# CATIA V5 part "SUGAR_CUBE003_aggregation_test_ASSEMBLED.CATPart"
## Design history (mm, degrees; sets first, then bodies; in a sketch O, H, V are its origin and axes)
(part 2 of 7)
Body8 "sugar_cube003_Ab002"
  Line62: type PtDir, RefPoint Point10, Direction edge [XY plane of AxisSystem1 | ZX plane of AxisSystem1], Start 0, End 3048 {= Body8.X1}
  Line63: type PtDir, RefPoint Point10, Direction edge [XY plane of AxisSystem1 | ZX plane of AxisSystem1], Start 0, End 3657.6 {= Body8.X2}
  Line64: type PtDir, RefPoint Point10, Direction edge [YZ plane of AxisSystem1 | XY plane of AxisSystem1], Start 0, End 3962.4 {= Body8.Y1}
  Line65: type PtDir, RefPoint Point10, Direction edge [YZ plane of AxisSystem1 | XY plane of AxisSystem1], Start 0, End 4876.8 {= Body8.Y2}
  Line66: type PtDir, RefPoint Point10, Direction edge [ZX plane of AxisSystem1 | YZ plane of AxisSystem1], Start 0, End 3962.4 {= Body8.Z1}
  Line67: type PtDir, RefPoint Point10, Direction edge [ZX plane of AxisSystem1 | YZ plane of AxisSystem1], Start 0, End 4876.8 {= Body8.Z2}
  Plane89: type Normal, Curve Line62, RefPoint vertex of Line62
  Plane90: type Normal, Curve Line63, RefPoint vertex of Line63
  Plane91: type Normal, Curve Line64, RefPoint vertex of Line64
  Plane92: type Normal, Curve Line65, RefPoint vertex of Line65
  Plane93: type Normal, Curve Line66, RefPoint vertex of Line66
  Plane94: type Normal, Curve Line67, RefPoint vertex of Line67
  Plane95: type 3Points, Element1 Point10, Element2 vertex of Line64, Element3 vertex of Line62
  Intersect121: ToIntersect1 Plane91, ToIntersect2 Plane90
  Intersect122: ToIntersect1 Plane89, ToIntersect2 Plane91
  Intersect123: ToIntersect1 Plane89, ToIntersect2 Plane92
  Intersect124: ToIntersect1 Plane92, ToIntersect2 Plane90
  MultiSel7
  LineCorner7: Elements ({intersect ToIntersect1 Plane95, ToIntersect2 Intersect123}; {intersect ToIntersect1 Plane95, ToIntersect2 Intersect124}; {intersect ToIntersect1 Plane95, ToIntersect2 Intersect121}; {intersect ToIntersect1 Plane95, ToIntersect2 Intersect122})
  Pad26: profile LineCorner7, up to Plane93, opposite side up to Plane94, deactivated
  Plane96: type Offset, RefPlane Plane92, Offset 609.6 {= thickness}
  Plane97: type Offset, RefPlane Plane91, Offset 609.6 {= thickness}, reversed
  Plane98: type Offset, RefPlane Plane89, Offset 609.6 {= thickness}, reversed
  Plane99: type Offset, RefPlane Plane90, Offset 609.6 {= thickness}
  Plane100: type Offset, RefPlane Plane94, Offset 609.6 {= thickness}
  Plane101: type Offset, RefPlane Plane93, Offset 609.6 {= thickness}, reversed
  Intersect125: ToIntersect1 Plane96, ToIntersect2 Plane89
  Intersect126: ToIntersect1 Plane97, ToIntersect2 Plane89
  Intersect127: ToIntersect1 Plane100, ToIntersect2 Plane89
  Intersect128: ToIntersect1 Plane101, ToIntersect2 Plane89
  Trim73: Trimmed (Intersect125; Intersect128)
  Trim74: Trimmed (Trim73; Intersect126)
  Trim75: Trimmed (Trim74; Intersect127)
  Pocket30: profile Trim75, up to Plane99, deactivated
  Pad27: profile LineCorner7, up to Plane93, opposite side up to Plane94, deactivated
  Intersect129: ToIntersect1 Plane97, ToIntersect2 Plane90
  Intersect130: ToIntersect1 Plane90, ToIntersect2 Plane96
  Intersect131: ToIntersect1 Plane100, ToIntersect2 Plane90
  Intersect132: ToIntersect1 Plane101, ToIntersect2 Plane90
  Trim76: Trimmed (Intersect132; Intersect129)
  Trim77: Trimmed (Trim76; Intersect131)
  Trim78: Trimmed (Trim77; Intersect130)
  Pocket31: profile Trim78, up to Plane98, deactivated
  Intersect133: ToIntersect1 Plane99, ToIntersect2 Plane92
  Intersect134: ToIntersect1 Plane100, ToIntersect2 Plane92
  Intersect135: ToIntersect1 Plane92, ToIntersect2 Plane98
  Intersect136: ToIntersect1 Plane101, ToIntersect2 Plane92
  Trim79: Trimmed (Intersect133; Intersect136)
  Trim80: Trimmed (Trim79; Intersect135)
  Trim81: Trimmed (Trim80; Intersect134)
  Pad28: profile LineCorner7, up to Plane93, opposite side up to Plane94, deactivated
  Pocket32: profile Trim81, up to Plane97, deactivated
  Intersect137: ToIntersect1 Plane98, ToIntersect2 Plane91
  Intersect138: ToIntersect1 Plane100, ToIntersect2 Plane91
  Intersect139: ToIntersect1 Plane99, ToIntersect2 Plane91
  Intersect140: ToIntersect1 Plane101, ToIntersect2 Plane91
  Trim82: Trimmed (Intersect137; Intersect140)
  Trim83: Trimmed (Trim82; Intersect139)
  Trim84: Trimmed (Trim83; Intersect138)
  Pad29: profile LineCorner7, up to Plane93, opposite side up to Plane94, deactivated
  Pocket33: profile Trim84, up to Plane96, deactivated
Body9 "sugar_cube003_Ac002"
  Line68: type PtDir, RefPoint Point6, Direction edge [XY plane of AxisSystem1 | ZX plane of AxisSystem1], Start 0, End 5181.6 {= Body9.X1}
  Line69: type PtDir, RefPoint Point6, Direction edge [XY plane of AxisSystem1 | ZX plane of AxisSystem1], Start 0, End 3962.4 {= Body9.X2}
  Line70: type PtDir, RefPoint Point6, Direction edge [YZ plane of AxisSystem1 | XY plane of AxisSystem1], Start 0, End 5791.2 {= Body9.Y1}
  Line71: type PtDir, RefPoint Point6, Direction edge [YZ plane of AxisSystem1 | XY plane of AxisSystem1], Start 0, End 5181.6 {= Body9.Y2}
  Line72: type PtDir, RefPoint Point6, Direction edge [ZX plane of AxisSystem1 | YZ plane of AxisSystem1], Start 0, End 6096 {= Body9.Z1}
  Line73: type PtDir, RefPoint Point6, Direction edge [ZX plane of AxisSystem1 | YZ plane of AxisSystem1], Start 0, End 5791.2 {= Body9.Z2}
  Plane102: type Normal, Curve Line68, RefPoint vertex of Line68
  Plane103: type Normal, Curve Line69, RefPoint vertex of Line69
  Plane104: type Normal, Curve Line70, RefPoint vertex of Line70
  Plane105: type Normal, Curve Line71, RefPoint vertex of Line71
  Plane106: type Normal, Curve Line72, RefPoint vertex of Line72
  Plane107: type Normal, Curve Line73, RefPoint vertex of Line73
  Plane108: type 3Points, Element1 Point6, Element2 vertex of Line70, Element3 vertex of Line68
  Intersect141: ToIntersect1 Plane104, ToIntersect2 Plane103
  Intersect142: ToIntersect1 Plane102, ToIntersect2 Plane104
  Intersect143: ToIntersect1 Plane102, ToIntersect2 Plane105
  Intersect144: ToIntersect1 Plane105, ToIntersect2 Plane103
  MultiSel8
  LineCorner8: Elements ({intersect ToIntersect1 Plane108, ToIntersect2 Intersect143}; {intersect ToIntersect1 Plane108, ToIntersect2 Intersect144}; {intersect ToIntersect1 Plane108, ToIntersect2 Intersect141}; {intersect ToIntersect1 Plane108, ToIntersect2 Intersect142})
  Pad30: profile LineCorner8, up to Plane106, opposite side up to Plane107
  Plane109: type Offset, RefPlane Plane105, Offset 609.6 {= thickness}
  Plane110: type Offset, RefPlane Plane104, Offset 609.6 {= thickness}, reversed
  Plane111: type Offset, RefPlane Plane102, Offset 609.6 {= thickness}, reversed
  Plane112: type Offset, RefPlane Plane103, Offset 609.6 {= thickness}
  Plane113: type Offset, RefPlane Plane107, Offset 609.6 {= thickness}
  Plane114: type Offset, RefPlane Plane106, Offset 609.6 {= thickness}, reversed
  Intersect145: ToIntersect1 Plane109, ToIntersect2 Plane102
  Intersect146: ToIntersect1 Plane110, ToIntersect2 Plane102
  Intersect147: ToIntersect1 Plane113, ToIntersect2 Plane102
  Intersect148: ToIntersect1 Plane114, ToIntersect2 Plane102
  Trim85: Trimmed (Intersect145; Intersect148)
  Trim86: Trimmed (Trim85; Intersect146)
  Trim87: Trimmed (Trim86; Intersect147)
  Pocket34: profile Trim87, up to Plane112, deactivated
  Pad31: profile LineCorner8, up to Plane106, opposite side up to Plane107
  Intersect149: ToIntersect1 Plane110, ToIntersect2 Plane103
  Intersect150: ToIntersect1 Plane103, ToIntersect2 Plane109
  Intersect151: ToIntersect1 Plane113, ToIntersect2 Plane103
  Intersect152: ToIntersect1 Plane114, ToIntersect2 Plane103
  Trim88: Trimmed (Intersect152; Intersect149)
  Trim89: Trimmed (Trim88; Intersect151)
  Trim90: Trimmed (Trim89; Intersect150)
  Pocket35: profile Trim90, up to Plane111
  Intersect153: ToIntersect1 Plane112, ToIntersect2 Plane105
  Intersect154: ToIntersect1 Plane113, ToIntersect2 Plane105
  Intersect155: ToIntersect1 Plane105, ToIntersect2 Plane111
  Intersect156: ToIntersect1 Plane114, ToIntersect2 Plane105
  Trim91: Trimmed (Intersect153; Intersect156)
  Trim92: Trimmed (Trim91; Intersect155)
  Trim93: Trimmed (Trim92; Intersect154)
  Pad32: profile LineCorner8, up to Plane106, opposite side up to Plane107, deactivated
  Pocket36: profile Trim93, up to Plane110, deactivated
  Intersect157: ToIntersect1 Plane111, ToIntersect2 Plane104
  Intersect158: ToIntersect1 Plane113, ToIntersect2 Plane104
  Intersect159: ToIntersect1 Plane112, ToIntersect2 Plane104
  Intersect160: ToIntersect1 Plane114, ToIntersect2 Plane104
  Trim94: Trimmed (Intersect157; Intersect160)
  Trim95: Trimmed (Trim94; Intersect159)
  Trim96: Trimmed (Trim95; Intersect158)
  Pad33: profile LineCorner8, up to Plane106, opposite side up to Plane107, deactivated
  Pocket37: profile Trim96, up to Plane109, deactivated
Body10 "sugar_cube003_Ad002"
  Line74: type PtDir, RefPoint Point2, Direction edge [XY plane of AxisSystem1 | ZX plane of AxisSystem1], Start 0, End 5486.4 {= Body10.X1}
  Line75: type PtDir, RefPoint Point2, Direction edge [XY plane of AxisSystem1 | ZX plane of AxisSystem1], Start 0, End 4876.8 {= Body10.X2}
  Line76: type PtDir, RefPoint Point2, Direction edge [YZ plane of AxisSystem1 | XY plane of AxisSystem1], Start 0, End 3962.4 {= Body10.Y1}
  Line77: type PtDir, RefPoint Point2, Direction edge [YZ plane of AxisSystem1 | XY plane of AxisSystem1], Start 0, End 3962.4 {= Body10.Y2}
  Line78: type PtDir, RefPoint Point2, Direction edge [ZX plane of AxisSystem1 | YZ plane of AxisSystem1], Start 0, End 6096 {= Body10.Z1}
  Line79: type PtDir, RefPoint Point2, Direction edge [ZX plane of AxisSystem1 | YZ plane of AxisSystem1], Start 0, End 3657.6 {= Body10.Z2}
  Plane115: type Normal, Curve Line74, RefPoint vertex of Line74
  Plane116: type Normal, Curve Line75, RefPoint vertex of Line75
  Plane117: type Normal, Curve Line76, RefPoint vertex of Line76
  Plane118: type Normal, Curve Line77, RefPoint vertex of Line77
  Plane119: type Normal, Curve Line78, RefPoint vertex of Line78
  Plane120: type Normal, Curve Line79, RefPoint vertex of Line79
  Plane121: type 3Points, Element1 Point2, Element2 vertex of Line76, Element3 vertex of Line74
  Intersect161: ToIntersect1 Plane117, ToIntersect2 Plane116
  Intersect162: ToIntersect1 Plane115, ToIntersect2 Plane117
  Intersect163: ToIntersect1 Plane115, ToIntersect2 Plane118
  Intersect164: ToIntersect1 Plane118, ToIntersect2 Plane116
  MultiSel9
  LineCorner9: Elements ({intersect ToIntersect1 Plane121, ToIntersect2 Intersect163}; {intersect ToIntersect1 Plane121, ToIntersect2 Intersect164}; {intersect ToIntersect1 Plane121, ToIntersect2 Intersect161}; {intersect ToIntersect1 Plane121, ToIntersect2 Intersect162})
  Pad34: profile LineCorner9, up to Plane119, opposite side up to Plane120, deactivated
  Plane122: type Offset, RefPlane Plane118, Offset 609.6 {= thickness}
  Plane123: type Offset, RefPlane Plane117, Offset 609.6 {= thickness}, reversed
  Plane124: type Offset, RefPlane Plane115, Offset 609.6 {= thickness}, reversed
  Plane125: type Offset, RefPlane Plane116, Offset 609.6 {= thickness}
  Plane126: type Offset, RefPlane Plane120, Offset 609.6 {= thickness}
  Plane127: type Offset, RefPlane Plane119, Offset 609.6 {= thickness}, reversed
  Intersect165: ToIntersect1 Plane122, ToIntersect2 Plane115
  Intersect166: ToIntersect1 Plane123, ToIntersect2 Plane115
  Intersect167: ToIntersect1 Plane126, ToIntersect2 Plane115
  Intersect168: ToIntersect1 Plane127, ToIntersect2 Plane115
  Trim97: Trimmed (Intersect165; Intersect168)
  Trim98: Trimmed (Trim97; Intersect166)
  Trim99: Trimmed (Trim98; Intersect167)
  Pocket38: profile Trim99, up to Plane125, deactivated
  Pad35: profile LineCorner9, up to Plane119, opposite side up to Plane120, deactivated
  Intersect169: ToIntersect1 Plane123, ToIntersect2 Plane116
  Intersect170: ToIntersect1 Plane116, ToIntersect2 Plane122
  Intersect171: ToIntersect1 Plane126, ToIntersect2 Plane116
  Intersect172: ToIntersect1 Plane127, ToIntersect2 Plane116
  Trim100: Trimmed (Intersect172; Intersect169)
  Trim101: Trimmed (Trim100; Intersect171)
  Trim102: Trimmed (Trim101; Intersect170)
  Pocket39: profile Trim102, up to Plane124, deactivated
  Intersect173: ToIntersect1 Plane125, ToIntersect2 Plane118
  Intersect174: ToIntersect1 Plane126, ToIntersect2 Plane118
  Intersect175: ToIntersect1 Plane118, ToIntersect2 Plane124
  Intersect176: ToIntersect1 Plane127, ToIntersect2 Plane118
  Trim103: Trimmed (Intersect173; Intersect176)
  Trim104: Trimmed (Trim103; Intersect175)
  Trim105: Trimmed (Trim104; Intersect174)
  Pad36: profile LineCorner9, up to Plane119, opposite side up to Plane120, deactivated
  Pocket40: profile Trim105, up to Plane123, deactivated
  Intersect177: ToIntersect1 Plane124, ToIntersect2 Plane117
  Intersect178: ToIntersect1 Plane126, ToIntersect2 Plane117
  Intersect179: ToIntersect1 Plane125, ToIntersect2 Plane117
  Intersect180: ToIntersect1 Plane127, ToIntersect2 Plane117
  Trim106: Trimmed (Intersect177; Intersect180)
  Trim107: Trimmed (Trim106; Intersect179)
  Trim108: Trimmed (Trim107; Intersect178)
  Pad37: profile LineCorner9, up to Plane119, opposite side up to Plane120, deactivated
  Pocket41: profile Trim108, up to Plane122, deactivated
Body11 "sugar_cube003_Ae002"
  Line80: type PtDir, RefPoint Point98, Direction edge [XY plane of AxisSystem1 | ZX plane of AxisSystem1], Start 0, End 4267.2 {= Body11.X1}
  Line81: type PtDir, RefPoint Point98, Direction edge [XY plane of AxisSystem1 | ZX plane of AxisSystem1], Start 0, End 3657.6 {= Body11.X2}
  Line82: type PtDir, RefPoint Point98, Direction edge [YZ plane of AxisSystem1 | XY plane of AxisSystem1], Start 0, End 5486.4 {= Body11.Y1}
  Line83: type PtDir, RefPoint Point98, Direction edge [YZ plane of AxisSystem1 | XY plane of AxisSystem1], Start 0, End 3048 {= Body11.Y2}
  Line84: type PtDir, RefPoint Point98, Direction edge [ZX plane of AxisSystem1 | YZ plane of AxisSystem1], Start 0, End 5181.6 {= Body11.Z1}
  Line85: type PtDir, RefPoint Point98, Direction edge [ZX plane of AxisSystem1 | YZ plane of AxisSystem1], Start 0, End 3048 {= Body11.Z2}
  Plane128: type Normal, Curve Line80, RefPoint vertex of Line80
  Plane129: type Normal, Curve Line81, RefPoint vertex of Line81
  Plane130: type Normal, Curve Line82, RefPoint vertex of Line82
  Plane131: type Normal, Curve Line83, RefPoint vertex of Line83
  Plane132: type Normal, Curve Line84, RefPoint vertex of Line84
  Plane133: type Normal, Curve Line85, RefPoint vertex of Line85
  Plane134: type 3Points, Element1 Point98, Element2 vertex of Line82, Element3 vertex of Line80
  Intersect181: ToIntersect1 Plane130, ToIntersect2 Plane129
  Intersect182: ToIntersect1 Plane128, ToIntersect2 Plane130
  Intersect183: ToIntersect1 Plane128, ToIntersect2 Plane131
  Intersect184: ToIntersect1 Plane131, ToIntersect2 Plane129
  MultiSel10
  LineCorner10: Elements ({intersect ToIntersect1 Plane134, ToIntersect2 Intersect183}; {intersect ToIntersect1 Plane134, ToIntersect2 Intersect184}; {intersect ToIntersect1 Plane134, ToIntersect2 Intersect181}; {intersect ToIntersect1 Plane134, ToIntersect2 Intersect182})
  Pad38: profile LineCorner10, up to Plane132, opposite side up to Plane133, deactivated
  Plane135: type Offset, RefPlane Plane131, Offset 609.6 {= thickness}
  Plane136: type Offset, RefPlane Plane130, Offset 609.6 {= thickness}, reversed
  Plane137: type Offset, RefPlane Plane128, Offset 609.6 {= thickness}, reversed
  Plane138: type Offset, RefPlane Plane129, Offset 609.6 {= thickness}
  Plane139: type Offset, RefPlane Plane133, Offset 609.6 {= thickness}
  Plane140: type Offset, RefPlane Plane132, Offset 609.6 {= thickness}, reversed
  Intersect185: ToIntersect1 Plane135, ToIntersect2 Plane128
  Intersect186: ToIntersect1 Plane136, ToIntersect2 Plane128
  Intersect187: ToIntersect1 Plane139, ToIntersect2 Plane128
  Intersect188: ToIntersect1 Plane140, ToIntersect2 Plane128
  Trim109: Trimmed (Intersect185; Intersect188)
  Trim110: Trimmed (Trim109; Intersect186)
  Trim111: Trimmed (Trim110; Intersect187)
  Pocket42: profile Trim111, up to Plane138, deactivated
  Pad39: profile LineCorner10, up to Plane132, opposite side up to Plane133, deactivated
  Intersect189: ToIntersect1 Plane136, ToIntersect2 Plane129
  Intersect190: ToIntersect1 Plane129, ToIntersect2 Plane135
  Intersect191: ToIntersect1 Plane139, ToIntersect2 Plane129
  Intersect192: ToIntersect1 Plane140, ToIntersect2 Plane129
  Trim112: Trimmed (Intersect192; Intersect189)
  Trim113: Trimmed (Trim112; Intersect191)
  Trim114: Trimmed (Trim113; Intersect190)
  Pocket43: profile Trim114, up to Plane137, deactivated
  Intersect193: ToIntersect1 Plane138, ToIntersect2 Plane131
  Intersect194: ToIntersect1 Plane139, ToIntersect2 Plane131
  Intersect195: ToIntersect1 Plane131, ToIntersect2 Plane137
  Intersect196: ToIntersect1 Plane140, ToIntersect2 Plane131
  Trim115: Trimmed (Intersect193; Intersect196)
  Trim116: Trimmed (Trim115; Intersect195)
  Trim117: Trimmed (Trim116; Intersect194)
  Pad40: profile LineCorner10, up to Plane132, opposite side up to Plane133
  Pocket44: profile Trim117, up to Plane136
  Intersect197: ToIntersect1 Plane137, ToIntersect2 Plane130
  Intersect198: ToIntersect1 Plane139, ToIntersect2 Plane130
  Intersect199: ToIntersect1 Plane138, ToIntersect2 Plane130
  Intersect200: ToIntersect1 Plane140, ToIntersect2 Plane130
  Trim118: Trimmed (Intersect197; Intersect200)
  Trim119: Trimmed (Trim118; Intersect199)
  Trim120: Trimmed (Trim119; Intersect198)
  Pad41: profile LineCorner10, up to Plane132, opposite side up to Plane133, deactivated
  Pocket45: profile Trim120, up to Plane135, deactivated
Body12 "sugar_cube003_Aa003"
  Line86: type PtDir, RefPoint Point15, Direction edge [XY plane of AxisSystem1 | ZX plane of AxisSystem1], Start 0, End 3048 {= Body12.X1}
  Line87: type PtDir, RefPoint Point15, Direction edge [XY plane of AxisSystem1 | ZX plane of AxisSystem1], Start 0, End 3657.6 {= Body12.X2}
  Line88: type PtDir, RefPoint Point15, Direction edge [YZ plane of AxisSystem1 | XY plane of AxisSystem1], Start 0, End 6096 {= Body12.Y1}
  Line89: type PtDir, RefPoint Point15, Direction edge [YZ plane of AxisSystem1 | XY plane of AxisSystem1], Start 0, End 6096 {= Body12.Y2}
  Line90: type PtDir, RefPoint Point15, Direction edge [ZX plane of AxisSystem1 | YZ plane of AxisSystem1], Start 0, End 4876.8 {= Body12.Z1}
  Line91: type PtDir, RefPoint Point15, Direction edge [ZX plane of AxisSystem1 | YZ plane of AxisSystem1], Start 0, End 3962.4 {= Body12.Z2}
  Plane141: type Normal, Curve Line86, RefPoint vertex of Line86
  Plane142: type Normal, Curve Line87, RefPoint vertex of Line87
  Plane143: type Normal, Curve Line88, RefPoint vertex of Line88
  Plane144: type Normal, Curve Line89, RefPoint vertex of Line89
  Plane145: type Normal, Curve Line90, RefPoint vertex of Line90
  Plane146: type Normal, Curve Line91, RefPoint vertex of Line91
  Plane147: type 3Points, Element1 Point15, Element2 vertex of Line88, Element3 vertex of Line86
  Intersect201: ToIntersect1 Plane143, ToIntersect2 Plane142
  Intersect202: ToIntersect1 Plane141, ToIntersect2 Plane143
  Intersect203: ToIntersect1 Plane141, ToIntersect2 Plane144
  Intersect204: ToIntersect1 Plane144, ToIntersect2 Plane142
  MultiSel11
  LineCorner11: Elements ({intersect ToIntersect1 Plane147, ToIntersect2 Intersect203}; {intersect ToIntersect1 Plane147, ToIntersect2 Intersect204}; {intersect ToIntersect1 Plane147, ToIntersect2 Intersect201}; {intersect ToIntersect1 Plane147, ToIntersect2 Intersect202})
  Pad42: profile LineCorner11, up to Plane145, opposite side up to Plane146, deactivated
  Plane148: type Offset, RefPlane Plane144, Offset 609.6 {= thickness}
  Plane149: type Offset, RefPlane Plane143, Offset 609.6 {= thickness}, reversed
  Plane150: type Offset, RefPlane Plane141, Offset 609.6 {= thickness}, reversed
  Plane151: type Offset, RefPlane Plane142, Offset 609.6 {= thickness}
  Plane152: type Offset, RefPlane Plane146, Offset 609.6 {= thickness}
  Plane153: type Offset, RefPlane Plane145, Offset 609.6 {= thickness}, reversed
  Intersect205: ToIntersect1 Plane148, ToIntersect2 Plane141
  Intersect206: ToIntersect1 Plane149, ToIntersect2 Plane141
  Intersect207: ToIntersect1 Plane152, ToIntersect2 Plane141
  Intersect208: ToIntersect1 Plane153, ToIntersect2 Plane141
  Trim121: Trimmed (Intersect205; Intersect208)
  Trim122: Trimmed (Trim121; Intersect206)
  Trim123: Trimmed (Trim122; Intersect207)
  Pocket46: profile Trim123, up to Plane151, deactivated
  Pad43: profile LineCorner11, up to Plane145, opposite side up to Plane146, deactivated
  Intersect209: ToIntersect1 Plane149, ToIntersect2 Plane142
  Intersect210: ToIntersect1 Plane142, ToIntersect2 Plane148
  Intersect211: ToIntersect1 Plane152, ToIntersect2 Plane142
  Intersect212: ToIntersect1 Plane153, ToIntersect2 Plane142
  Trim124: Trimmed (Intersect212; Intersect209)
  Trim125: Trimmed (Trim124; Intersect211)
  Trim126: Trimmed (Trim125; Intersect210)
  Pocket47: profile Trim126, up to Plane150, deactivated
  Intersect213: ToIntersect1 Plane151, ToIntersect2 Plane144
  Intersect214: ToIntersect1 Plane152, ToIntersect2 Plane144
  Intersect215: ToIntersect1 Plane144, ToIntersect2 Plane150
  Intersect216: ToIntersect1 Plane153, ToIntersect2 Plane144
  Trim127: Trimmed (Intersect213; Intersect216)
  Trim128: Trimmed (Trim127; Intersect215)
  Trim129: Trimmed (Trim128; Intersect214)
  Pad44: profile LineCorner11, up to Plane145, opposite side up to Plane146, deactivated
  Pocket48: profile Trim129, up to Plane149, deactivated
  Intersect217: ToIntersect1 Plane150, ToIntersect2 Plane143
  Intersect218: ToIntersect1 Plane152, ToIntersect2 Plane143
  Intersect219: ToIntersect1 Plane151, ToIntersect2 Plane143
  Intersect220: ToIntersect1 Plane153, ToIntersect2 Plane143
  Trim130: Trimmed (Intersect217; Intersect220)
  Trim131: Trimmed (Trim130; Intersect219)
  Trim132: Trimmed (Trim131; Intersect218)
  Pad45: profile LineCorner11, up to Plane145, opposite side up to Plane146, deactivated
  Pocket49: profile Trim132, up to Plane148, deactivated
Body13 "sugar_cube003_Ab003"
  Line92: type PtDir, RefPoint Point11, Direction edge [XY plane of AxisSystem1 | ZX plane of AxisSystem1], Start 0, End 4876.8 {= Body13.X1}
  Line93: type PtDir, RefPoint Point11, Direction edge [XY plane of AxisSystem1 | ZX plane of AxisSystem1], Start 0, End 6096 {= Body13.X2}
  Line94: type PtDir, RefPoint Point11, Direction edge [YZ plane of AxisSystem1 | XY plane of AxisSystem1], Start 0, End 6096 {= Body13.Y1}
  Line95: type PtDir, RefPoint Point11, Direction edge [YZ plane of AxisSystem1 | XY plane of AxisSystem1], Start 0, End 3962.4 {= Body13.Y2}
  Line96: type PtDir, RefPoint Point11, Direction edge [ZX plane of AxisSystem1 | YZ plane of AxisSystem1], Start 0, End 4876.8 {= Body13.Z1}
  Line97: type PtDir, RefPoint Point11, Direction edge [ZX plane of AxisSystem1 | YZ plane of AxisSystem1], Start 0, End 3962.4 {= Body13.Z2}
  Plane154: type Normal, Curve Line92, RefPoint vertex of Line92
  Plane155: type Normal, Curve Line93, RefPoint vertex of Line93
  Plane156: type Normal, Curve Line94, RefPoint vertex of Line94
  Plane157: type Normal, Curve Line95, RefPoint vertex of Line95
  Plane158: type Normal, Curve Line96, RefPoint vertex of Line96
  Plane159: type Normal, Curve Line97, RefPoint vertex of Line97
  Plane160: type 3Points, Element1 Point11, Element2 vertex of Line94, Element3 vertex of Line92
  Intersect221: ToIntersect1 Plane156, ToIntersect2 Plane155
  Intersect222: ToIntersect1 Plane154, ToIntersect2 Plane156
  Intersect223: ToIntersect1 Plane154, ToIntersect2 Plane157
  Intersect224: ToIntersect1 Plane157, ToIntersect2 Plane155
  MultiSel12
  LineCorner12: Elements ({intersect ToIntersect1 Plane160, ToIntersect2 Intersect223}; {intersect ToIntersect1 Plane160, ToIntersect2 Intersect224}; {intersect ToIntersect1 Plane160, ToIntersect2 Intersect221}; {intersect ToIntersect1 Plane160, ToIntersect2 Intersect222})
  Pad46: profile LineCorner12, up to Plane158, opposite side up to Plane159
  Plane161: type Offset, RefPlane Plane157, Offset 609.6 {= thickness}
  Plane162: type Offset, RefPlane Plane156, Offset 609.6 {= thickness}, reversed
  Plane163: type Offset, RefPlane Plane154, Offset 609.6 {= thickness}, reversed
  Plane164: type Offset, RefPlane Plane155, Offset 609.6 {= thickness}
  Plane165: type Offset, RefPlane Plane159, Offset 609.6 {= thickness}
  Plane166: type Offset, RefPlane Plane158, Offset 609.6 {= thickness}, reversed
  Intersect225: ToIntersect1 Plane161, ToIntersect2 Plane154
  Intersect226: ToIntersect1 Plane162, ToIntersect2 Plane154
  Intersect227: ToIntersect1 Plane165, ToIntersect2 Plane154
  Intersect228: ToIntersect1 Plane166, ToIntersect2 Plane154
  Trim133: Trimmed (Intersect225; Intersect228)
  Trim134: Trimmed (Trim133; Intersect226)
  Trim135: Trimmed (Trim134; Intersect227)
  Pocket50: profile Trim135, up to Plane164, deactivated
  Pad47: profile LineCorner12, up to Plane158, opposite side up to Plane159, deactivated
  Intersect229: ToIntersect1 Plane162, ToIntersect2 Plane155
  Intersect230: ToIntersect1 Plane155, ToIntersect2 Plane161
  Intersect231: ToIntersect1 Plane165, ToIntersect2 Plane155
  Intersect232: ToIntersect1 Plane166, ToIntersect2 Plane155
  Trim136: Trimmed (Intersect232; Intersect229)
  Trim137: Trimmed (Trim136; Intersect231)
  Trim138: Trimmed (Trim137; Intersect230)
  Pocket51: profile Trim138, up to Plane163, deactivated
  Intersect233: ToIntersect1 Plane164, ToIntersect2 Plane157
  Intersect234: ToIntersect1 Plane165, ToIntersect2 Plane157
  Intersect235: ToIntersect1 Plane157, ToIntersect2 Plane163
  Intersect236: ToIntersect1 Plane166, ToIntersect2 Plane157
  Trim139: Trimmed (Intersect233; Intersect236)
  Trim140: Trimmed (Trim139; Intersect235)
  Trim141: Trimmed (Trim140; Intersect234)
  Pad48: profile LineCorner12, up to Plane158, opposite side up to Plane159, deactivated
  Pocket52: profile Trim141, up to Plane162, deactivated
  Intersect237: ToIntersect1 Plane163, ToIntersect2 Plane156
  Intersect238: ToIntersect1 Plane165, ToIntersect2 Plane156
  Intersect239: ToIntersect1 Plane164, ToIntersect2 Plane156
  Intersect240: ToIntersect1 Plane166, ToIntersect2 Plane156
  Trim142: Trimmed (Intersect237; Intersect240)
  Trim143: Trimmed (Trim142; Intersect239)
  Trim144: Trimmed (Trim143; Intersect238)
  Pad49: profile LineCorner12, up to Plane158, opposite side up to Plane159
  Pocket53: profile Trim144, up to Plane161
Body14 "sugar_cube003_Ac003"
  Line98: type PtDir, RefPoint Point7, Direction edge [XY plane of AxisSystem1 | ZX plane of AxisSystem1], Start 0, End 4876.8 {= Body14.X1}
  Line99: type PtDir, RefPoint Point7, Direction edge [XY plane of AxisSystem1 | ZX plane of AxisSystem1], Start 0, End 4267.2 {= Body14.X2}
  Line100: type PtDir, RefPoint Point7, Direction edge [YZ plane of AxisSystem1 | XY plane of AxisSystem1], Start 0, End 5486.4 {= Body14.Y1}
  Line101: type PtDir, RefPoint Point7, Direction edge [YZ plane of AxisSystem1 | XY plane of AxisSystem1], Start 0, End 4267.2 {= Body14.Y2}
  Line102: type PtDir, RefPoint Point7, Direction edge [ZX plane of AxisSystem1 | YZ plane of AxisSystem1], Start 0, End 3962.4 {= Body14.Z1}
  Line103: type PtDir, RefPoint Point7, Direction edge [ZX plane of AxisSystem1 | YZ plane of AxisSystem1], Start 0, End 4876.8 {= Body14.Z2}
  Plane167: type Normal, Curve Line98, RefPoint vertex of Line98
  Plane168: type Normal, Curve Line99, RefPoint vertex of Line99
  Plane169: type Normal, Curve Line100, RefPoint vertex of Line100
  Plane170: type Normal, Curve Line101, RefPoint vertex of Line101
  Plane171: type Normal, Curve Line102, RefPoint vertex of Line102
  Plane172: type Normal, Curve Line103, RefPoint vertex of Line103
  Plane173: type 3Points, Element1 Point7, Element2 vertex of Line100, Element3 vertex of Line98
  Intersect241: ToIntersect1 Plane169, ToIntersect2 Plane168
  Intersect242: ToIntersect1 Plane167, ToIntersect2 Plane169
  Intersect243: ToIntersect1 Plane167, ToIntersect2 Plane170
  Intersect244: ToIntersect1 Plane170, ToIntersect2 Plane168
  MultiSel13
  LineCorner13: Elements ({intersect ToIntersect1 Plane173, ToIntersect2 Intersect243}; {intersect ToIntersect1 Plane173, ToIntersect2 Intersect244}; {intersect ToIntersect1 Plane173, ToIntersect2 Intersect241}; {intersect ToIntersect1 Plane173, ToIntersect2 Intersect242})
  Pad50: profile LineCorner13, up to Plane171, opposite side up to Plane172, deactivated
  Plane174: type Offset, RefPlane Plane170, Offset 609.6 {= thickness}
  Plane175: type Offset, RefPlane Plane169, Offset 609.6 {= thickness}, reversed
  Plane176: type Offset, RefPlane Plane167, Offset 609.6 {= thickness}, reversed
  Plane177: type Offset, RefPlane Plane168, Offset 609.6 {= thickness}
  Plane178: type Offset, RefPlane Plane172, Offset 609.6 {= thickness}
  Plane179: type Offset, RefPlane Plane171, Offset 609.6 {= thickness}, reversed
  Intersect245: ToIntersect1 Plane174, ToIntersect2 Plane167
  Intersect246: ToIntersect1 Plane175, ToIntersect2 Plane167
  Intersect247: ToIntersect1 Plane178, ToIntersect2 Plane167
  Intersect248: ToIntersect1 Plane179, ToIntersect2 Plane167
  Trim145: Trimmed (Intersect245; Intersect248)
  Trim146: Trimmed (Trim145; Intersect246)
  Trim147: Trimmed (Trim146; Intersect247)
  Pocket54: profile Trim147, up to Plane177, deactivated
  Pad51: profile LineCorner13, up to Plane171, opposite side up to Plane172, deactivated
  Intersect249: ToIntersect1 Plane175, ToIntersect2 Plane168
  Intersect250: ToIntersect1 Plane168, ToIntersect2 Plane174
  Intersect251: ToIntersect1 Plane178, ToIntersect2 Plane168
  Intersect252: ToIntersect1 Plane179, ToIntersect2 Plane168
  Trim148: Trimmed (Intersect252; Intersect249)
  Trim149: Trimmed (Trim148; Intersect251)
  Trim150: Trimmed (Trim149; Intersect250)
  Pocket55: profile Trim150, up to Plane176, deactivated
  Intersect253: ToIntersect1 Plane177, ToIntersect2 Plane170
  Intersect254: ToIntersect1 Plane178, ToIntersect2 Plane170
  Intersect255: ToIntersect1 Plane170, ToIntersect2 Plane176
  Intersect256: ToIntersect1 Plane179, ToIntersect2 Plane170
  Trim151: Trimmed (Intersect253; Intersect256)
  Trim152: Trimmed (Trim151; Intersect255)
  Trim153: Trimmed (Trim152; Intersect254)
  Pad52: profile LineCorner13, up to Plane171, opposite side up to Plane172
  Pocket56: profile Trim153, up to Plane175
  Intersect257: ToIntersect1 Plane176, ToIntersect2 Plane169
  Intersect258: ToIntersect1 Plane178, ToIntersect2 Plane169
  Intersect259: ToIntersect1 Plane177, ToIntersect2 Plane169
  Intersect260: ToIntersect1 Plane179, ToIntersect2 Plane169
  Trim154: Trimmed (Intersect257; Intersect260)
  Trim155: Trimmed (Trim154; Intersect259)
  Trim156: Trimmed (Trim155; Intersect258)
  Pad53: profile LineCorner13, up to Plane171, opposite side up to Plane172, deactivated
  Pocket57: profile Trim156, up to Plane174, deactivated
Body15 "sugar_cube003_Ad003"
  Line104: type PtDir, RefPoint Point3, Direction edge [XY plane of AxisSystem1 | ZX plane of AxisSystem1], Start 0, End 4267.2 {= Body15.X1}
  Line105: type PtDir, RefPoint Point3, Direction edge [XY plane of AxisSystem1 | ZX plane of AxisSystem1], Start 0, End 3048 {= Body15.X2}
  Line106: type PtDir, RefPoint Point3, Direction edge [YZ plane of AxisSystem1 | XY plane of AxisSystem1], Start 0, End 5791.2 {= Body15.Y1}
  Line107: type PtDir, RefPoint Point3, Direction edge [YZ plane of AxisSystem1 | XY plane of AxisSystem1], Start 0, End 5791.2 {= Body15.Y2}
  Line108: type PtDir, RefPoint Point3, Direction edge [ZX plane of AxisSystem1 | YZ plane of AxisSystem1], Start 0, End 4267.2 {= Body15.Z1}
  Line109: type PtDir, RefPoint Point3, Direction edge [ZX plane of AxisSystem1 | YZ plane of AxisSystem1], Start 0, End 3657.6 {= Body15.Z2}
  Plane180: type Normal, Curve Line104, RefPoint vertex of Line104
  Plane181: type Normal, Curve Line105, RefPoint vertex of Line105
  Plane182: type Normal, Curve Line106, RefPoint vertex of Line106
  Plane183: type Normal, Curve Line107, RefPoint vertex of Line107
  Plane184: type Normal, Curve Line108, RefPoint vertex of Line108
  Plane185: type Normal, Curve Line109, RefPoint vertex of Line109
  Plane186: type 3Points, Element1 Point3, Element2 vertex of Line106, Element3 vertex of Line104
  Intersect261: ToIntersect1 Plane182, ToIntersect2 Plane181
  Intersect262: ToIntersect1 Plane180, ToIntersect2 Plane182
  Intersect263: ToIntersect1 Plane180, ToIntersect2 Plane183
  Intersect264: ToIntersect1 Plane183, ToIntersect2 Plane181
  MultiSel14
  LineCorner14: Elements ({intersect ToIntersect1 Plane186, ToIntersect2 Intersect263}; {intersect ToIntersect1 Plane186, ToIntersect2 Intersect264}; {intersect ToIntersect1 Plane186, ToIntersect2 Intersect261}; {intersect ToIntersect1 Plane186, ToIntersect2 Intersect262})
  Pad54: profile LineCorner14, up to Plane184, opposite side up to Plane185
  Plane187: type Offset, RefPlane Plane183, Offset 609.6 {= thickness}
  Plane188: type Offset, RefPlane Plane182, Offset 609.6 {= thickness}, reversed
  Plane189: type Offset, RefPlane Plane180, Offset 609.6 {= thickness}, reversed
  Plane190: type Offset, RefPlane Plane181, Offset 609.6 {= thickness}
  Plane191: type Offset, RefPlane Plane185, Offset 609.6 {= thickness}
  Plane192: type Offset, RefPlane Plane184, Offset 609.6 {= thickness}, reversed
  Intersect265: ToIntersect1 Plane187, ToIntersect2 Plane180
  Intersect266: ToIntersect1 Plane188, ToIntersect2 Plane180
  Intersect267: ToIntersect1 Plane191, ToIntersect2 Plane180
  Intersect268: ToIntersect1 Plane192, ToIntersect2 Plane180
  Trim157: Trimmed (Intersect265; Intersect268)
  Trim158: Trimmed (Trim157; Intersect266)
  Trim159: Trimmed (Trim158; Intersect267)
  Pocket58: profile Trim159, up to Plane190
  Pad55: profile LineCorner14, up to Plane184, opposite side up to Plane185, deactivated
  Intersect269: ToIntersect1 Plane188, ToIntersect2 Plane181
  Intersect270: ToIntersect1 Plane181, ToIntersect2 Plane187
  Intersect271: ToIntersect1 Plane191, ToIntersect2 Plane181
  Intersect272: ToIntersect1 Plane192, ToIntersect2 Plane181
  Trim160: Trimmed (Intersect272; Intersect269)
  Trim161: Trimmed (Trim160; Intersect271)
  Trim162: Trimmed (Trim161; Intersect270)
  Pocket59: profile Trim162, up to Plane189, deactivated
  Intersect273: ToIntersect1 Plane190, ToIntersect2 Plane183
  Intersect274: ToIntersect1 Plane191, ToIntersect2 Plane183
  Intersect275: ToIntersect1 Plane183, ToIntersect2 Plane189
  Intersect276: ToIntersect1 Plane192, ToIntersect2 Plane183
  Trim163: Trimmed (Intersect273; Intersect276)
  Trim164: Trimmed (Trim163; Intersect275)
  Trim165: Trimmed (Trim164; Intersect274)
  Pad56: profile LineCorner14, up to Plane184, opposite side up to Plane185, deactivated
  Pocket60: profile Trim165, up to Plane188, deactivated
  Intersect277: ToIntersect1 Plane189, ToIntersect2 Plane182
  Intersect278: ToIntersect1 Plane191, ToIntersect2 Plane182
  Intersect279: ToIntersect1 Plane190, ToIntersect2 Plane182
  Intersect280: ToIntersect1 Plane192, ToIntersect2 Plane182
  Trim166: Trimmed (Intersect277; Intersect280)
  Trim167: Trimmed (Trim166; Intersect279)
  Trim168: Trimmed (Trim167; Intersect278)
  Pad57: profile LineCorner14, up to Plane184, opposite side up to Plane185, deactivated
  Pocket61: profile Trim168, up to Plane187, deactivated
Body16 "sugar_cube003_Ae003"
  Line110: type PtDir, RefPoint Point99, Direction edge [XY plane of AxisSystem1 | ZX plane of AxisSystem1], Start 0, End 5181.6 {= Body16.X1}
  Line111: type PtDir, RefPoint Point99, Direction edge [XY plane of AxisSystem1 | ZX plane of AxisSystem1], Start 0, End 5791.2 {= Body16.X2}
  Line112: type PtDir, RefPoint Point99, Direction edge [YZ plane of AxisSystem1 | XY plane of AxisSystem1], Start 0, End 3657.6 {= Body16.Y1}
  Line113: type PtDir, RefPoint Point99, Direction edge [YZ plane of AxisSystem1 | XY plane of AxisSystem1], Start 0, End 6096 {= Body16.Y2}
  Line114: type PtDir, RefPoint Point99, Direction edge [ZX plane of AxisSystem1 | YZ plane of AxisSystem1], Start 0, End 5181.6 {= Body16.Z1}
  Line115: type PtDir, RefPoint Point99, Direction edge [ZX plane of AxisSystem1 | YZ plane of AxisSystem1], Start 0, End 4267.2 {= Body16.Z2}
  Plane193: type Normal, Curve Line110, RefPoint vertex of Line110
  Plane194: type Normal, Curve Line111, RefPoint vertex of Line111
  Plane195: type Normal, Curve Line112, RefPoint vertex of Line112
  Plane196: type Normal, Curve Line113, RefPoint vertex of Line113
  Plane197: type Normal, Curve Line114, RefPoint vertex of Line114
  Plane198: type Normal, Curve Line115, RefPoint vertex of Line115
  Plane199: type 3Points, Element1 Point99, Element2 vertex of Line112, Element3 vertex of Line110
  Intersect281: ToIntersect1 Plane195, ToIntersect2 Plane194
  Intersect282: ToIntersect1 Plane193, ToIntersect2 Plane195
  Intersect283: ToIntersect1 Plane193, ToIntersect2 Plane196
  Intersect284: ToIntersect1 Plane196, ToIntersect2 Plane194
  MultiSel15
  LineCorner15: Elements ({intersect ToIntersect1 Plane199, ToIntersect2 Intersect283}; {intersect ToIntersect1 Plane199, ToIntersect2 Intersect284}; {intersect ToIntersect1 Plane199, ToIntersect2 Intersect281}; {intersect ToIntersect1 Plane199, ToIntersect2 Intersect282})
  Pad58: profile LineCorner15, up to Plane197, opposite side up to Plane198, deactivated
  Plane200: type Offset, RefPlane Plane196, Offset 609.6 {= thickness}
  Plane201: type Offset, RefPlane Plane195, Offset 609.6 {= thickness}, reversed
  Plane202: type Offset, RefPlane Plane193, Offset 609.6 {= thickness}, reversed
  Plane203: type Offset, RefPlane Plane194, Offset 609.6 {= thickness}
  Plane204: type Offset, RefPlane Plane198, Offset 609.6 {= thickness}
  Plane205: type Offset, RefPlane Plane197, Offset 609.6 {= thickness}, reversed
  Intersect285: ToIntersect1 Plane200, ToIntersect2 Plane193
  Intersect286: ToIntersect1 Plane201, ToIntersect2 Plane193
  Intersect287: ToIntersect1 Plane204, ToIntersect2 Plane193
  Intersect288: ToIntersect1 Plane205, ToIntersect2 Plane193
  Trim169: Trimmed (Intersect285; Intersect288)
  Trim170: Trimmed (Trim169; Intersect286)
  Trim171: Trimmed (Trim170; Intersect287)
  Pocket62: profile Trim171, up to Plane203, deactivated
  Pad59: profile LineCorner15, up to Plane197, opposite side up to Plane198, deactivated
  Intersect289: ToIntersect1 Plane201, ToIntersect2 Plane194
  Intersect290: ToIntersect1 Plane194, ToIntersect2 Plane200
  Intersect291: ToIntersect1 Plane204, ToIntersect2 Plane194
  Intersect292: ToIntersect1 Plane205, ToIntersect2 Plane194
  Trim172: Trimmed (Intersect292; Intersect289)
  Trim173: Trimmed (Trim172; Intersect291)
  Trim174: Trimmed (Trim173; Intersect290)
  Pocket63: profile Trim174, up to Plane202, deactivated
  Intersect293: ToIntersect1 Plane203, ToIntersect2 Plane196
  Intersect294: ToIntersect1 Plane204, ToIntersect2 Plane196
  Intersect295: ToIntersect1 Plane196, ToIntersect2 Plane202
  Intersect296: ToIntersect1 Plane205, ToIntersect2 Plane196
  Trim175: Trimmed (Intersect293; Intersect296)
  Trim176: Trimmed (Trim175; Intersect295)
  Trim177: Trimmed (Trim176; Intersect294)
  Pad60: profile LineCorner15, up to Plane197, opposite side up to Plane198
  Pocket64: profile Trim177, up to Plane201
  Intersect297: ToIntersect1 Plane202, ToIntersect2 Plane195
  Intersect298: ToIntersect1 Plane204, ToIntersect2 Plane195
  Intersect299: ToIntersect1 Plane203, ToIntersect2 Plane195
  Intersect300: ToIntersect1 Plane205, ToIntersect2 Plane195
  Trim178: Trimmed (Intersect297; Intersect300)
  Trim179: Trimmed (Trim178; Intersect299)
  Trim180: Trimmed (Trim179; Intersect298)
  Pad61: profile LineCorner15, up to Plane197, opposite side up to Plane198, deactivated
  Pocket65: profile Trim180, up to Plane200, deactivated
Body17 "sugar_cube003_Aa004"
  Line116: type PtDir, RefPoint Point16, Direction edge [XY plane of AxisSystem1 | ZX plane of AxisSystem1], Start 0, End 5181.6 {= Body17.X1}
  Line117: type PtDir, RefPoint Point16, Direction edge [XY plane of AxisSystem1 | ZX plane of AxisSystem1], Start 0, End 3657.6 {= Body17.X2}
  Line118: type PtDir, RefPoint Point16, Direction edge [YZ plane of AxisSystem1 | XY plane of AxisSystem1], Start 0, End 3657.6 {= Body17.Y1}
  Line119: type PtDir, RefPoint Point16, Direction edge [YZ plane of AxisSystem1 | XY plane of AxisSystem1], Start 0, End 4572 {= Body17.Y2}
  Line120: type PtDir, RefPoint Point16, Direction edge [ZX plane of AxisSystem1 | YZ plane of AxisSystem1], Start 0, End 3048 {= Body17.Z1}
  Line121: type PtDir, RefPoint Point16, Direction edge [ZX plane of AxisSystem1 | YZ plane of AxisSystem1], Start 0, End 3352.8 {= Body17.Z2}
  Plane206: type Normal, Curve Line116, RefPoint vertex of Line116
  Plane207: type Normal, Curve Line117, RefPoint vertex of Line117
  Plane208: type Normal, Curve Line118, RefPoint vertex of Line118
  Plane209: type Normal, Curve Line119, RefPoint vertex of Line119
  Plane210: type Normal, Curve Line120, RefPoint vertex of Line120
  Plane211: type Normal, Curve Line121, RefPoint vertex of Line121
  Plane212: type 3Points, Element1 Point16, Element2 vertex of Line118, Element3 vertex of Line116
  Intersect301: ToIntersect1 Plane208, ToIntersect2 Plane207
  Intersect302: ToIntersect1 Plane206, ToIntersect2 Plane208
  Intersect303: ToIntersect1 Plane206, ToIntersect2 Plane209
  Intersect304: ToIntersect1 Plane209, ToIntersect2 Plane207
  MultiSel16
  LineCorner16: Elements ({intersect ToIntersect1 Plane212, ToIntersect2 Intersect303}; {intersect ToIntersect1 Plane212, ToIntersect2 Intersect304}; {intersect ToIntersect1 Plane212, ToIntersect2 Intersect301}; {intersect ToIntersect1 Plane212, ToIntersect2 Intersect302})
  Pad62: profile LineCorner16, up to Plane210, opposite side up to Plane211
  Plane213: type Offset, RefPlane Plane209, Offset 609.6 {= thickness}
  Plane214: type Offset, RefPlane Plane208, Offset 609.6 {= thickness}, reversed
  Plane215: type Offset, RefPlane Plane206, Offset 609.6 {= thickness}, reversed
  Plane216: type Offset, RefPlane Plane207, Offset 609.6 {= thickness}
  Plane217: type Offset, RefPlane Plane211, Offset 609.6 {= thickness}
  Plane218: type Offset, RefPlane Plane210, Offset 609.6 {= thickness}, reversed
  Intersect305: ToIntersect1 Plane213, ToIntersect2 Plane206
  Intersect306: ToIntersect1 Plane214, ToIntersect2 Plane206
  Intersect307: ToIntersect1 Plane217, ToIntersect2 Plane206
  Intersect308: ToIntersect1 Plane218, ToIntersect2 Plane206
  Trim181: Trimmed (Intersect305; Intersect308)
  Trim182: Trimmed (Trim181; Intersect306)
  Trim183: Trimmed (Trim182; Intersect307)
  Pocket66: profile Trim183, up to Plane216, deactivated
  Pad63: profile LineCorner16, up to Plane210, opposite side up to Plane211, deactivated
  Intersect309: ToIntersect1 Plane214, ToIntersect2 Plane207
  Intersect310: ToIntersect1 Plane207, ToIntersect2 Plane213
  Intersect311: ToIntersect1 Plane217, ToIntersect2 Plane207
  Intersect312: ToIntersect1 Plane218, ToIntersect2 Plane207
  Trim184: Trimmed (Intersect312; Intersect309)
  Trim185: Trimmed (Trim184; Intersect311)
  Trim186: Trimmed (Trim185; Intersect310)
  Pocket67: profile Trim186, up to Plane215, deactivated
  Intersect313: ToIntersect1 Plane216, ToIntersect2 Plane209
  Intersect314: ToIntersect1 Plane217, ToIntersect2 Plane209
  Intersect315: ToIntersect1 Plane209, ToIntersect2 Plane215
  Intersect316: ToIntersect1 Plane218, ToIntersect2 Plane209
  Trim187: Trimmed (Intersect313; Intersect316)
  Trim188: Trimmed (Trim187; Intersect315)
  Trim189: Trimmed (Trim188; Intersect314)
  Pad64: profile LineCorner16, up to Plane210, opposite side up to Plane211, deactivated
  Pocket68: profile Trim189, up to Plane214, deactivated
  Intersect317: ToIntersect1 Plane215, ToIntersect2 Plane208
  Intersect318: ToIntersect1 Plane217, ToIntersect2 Plane208
  Intersect319: ToIntersect1 Plane216, ToIntersect2 Plane208
  Intersect320: ToIntersect1 Plane218, ToIntersect2 Plane208
  Trim190: Trimmed (Intersect317; Intersect320)
  Trim191: Trimmed (Trim190; Intersect319)
  Trim192: Trimmed (Trim191; Intersect318)
  Pad65: profile LineCorner16, up to Plane210, opposite side up to Plane211, deactivated
  Pocket69: profile Trim192, up to Plane213, deactivated
Body18 "sugar_cube003_Ab004"
  Line122: type PtDir, RefPoint Point12, Direction edge [XY plane of AxisSystem1 | ZX plane of AxisSystem1], Start 0, End 3962.4 {= Body18.X1}
  Line123: type PtDir, RefPoint Point12, Direction edge [XY plane of AxisSystem1 | ZX plane of AxisSystem1], Start 0, End 5791.2 {= Body18.X2}
  Line124: type PtDir, RefPoint Point12, Direction edge [YZ plane of AxisSystem1 | XY plane of AxisSystem1], Start 0, End 5486.4 {= Body18.Y1}
  Line125: type PtDir, RefPoint Point12, Direction edge [YZ plane of AxisSystem1 | XY plane of AxisSystem1], Start 0, End 4876.8 {= Body18.Y2}
  Line126: type PtDir, RefPoint Point12, Direction edge [ZX plane of AxisSystem1 | YZ plane of AxisSystem1], Start 0, End 6096 {= Body18.Z1}
  Line127: type PtDir, RefPoint Point12, Direction edge [ZX plane of AxisSystem1 | YZ plane of AxisSystem1], Start 0, End 6096 {= Body18.Z2}
  Plane219: type Normal, Curve Line122, RefPoint vertex of Line122
  Plane220: type Normal, Curve Line123, RefPoint vertex of Line123
  Plane221: type Normal, Curve Line124, RefPoint vertex of Line124
  Plane222: type Normal, Curve Line125, RefPoint vertex of Line125
  Plane223: type Normal, Curve Line126, RefPoint vertex of Line126
  Plane224: type Normal, Curve Line127, RefPoint vertex of Line127
  Plane225: type 3Points, Element1 Point12, Element2 vertex of Line124, Element3 vertex of Line122
  Intersect321: ToIntersect1 Plane221, ToIntersect2 Plane220
  Intersect322: ToIntersect1 Plane219, ToIntersect2 Plane221
  Intersect323: ToIntersect1 Plane219, ToIntersect2 Plane222
  Intersect324: ToIntersect1 Plane222, ToIntersect2 Plane220
  MultiSel17
  LineCorner17: Elements ({intersect ToIntersect1 Plane225, ToIntersect2 Intersect323}; {intersect ToIntersect1 Plane225, ToIntersect2 Intersect324}; {intersect ToIntersect1 Plane225, ToIntersect2 Intersect321}; {intersect ToIntersect1 Plane225, ToIntersect2 Intersect322})
  Pad66: profile LineCorner17, up to Plane223, opposite side up to Plane224
  Plane226: type Offset, RefPlane Plane222, Offset 609.6 {= thickness}
  Plane227: type Offset, RefPlane Plane221, Offset 609.6 {= thickness}, reversed
  Plane228: type Offset, RefPlane Plane219, Offset 609.6 {= thickness}, reversed
  Plane229: type Offset, RefPlane Plane220, Offset 609.6 {= thickness}
  Plane230: type Offset, RefPlane Plane224, Offset 609.6 {= thickness}
  Plane231: type Offset, RefPlane Plane223, Offset 609.6 {= thickness}, reversed
  Intersect325: ToIntersect1 Plane226, ToIntersect2 Plane219
  Intersect326: ToIntersect1 Plane227, ToIntersect2 Plane219
  Intersect327: ToIntersect1 Plane230, ToIntersect2 Plane219
  Intersect328: ToIntersect1 Plane231, ToIntersect2 Plane219
  Trim193: Trimmed (Intersect325; Intersect328)
  Trim194: Trimmed (Trim193; Intersect326)
  Trim195: Trimmed (Trim194; Intersect327)
  Pocket70: profile Trim195, up to Plane229
  Pad67: profile LineCorner17, up to Plane223, opposite side up to Plane224, deactivated
  Intersect329: ToIntersect1 Plane227, ToIntersect2 Plane220
  Intersect330: ToIntersect1 Plane220, ToIntersect2 Plane226
  Intersect331: ToIntersect1 Plane230, ToIntersect2 Plane220
  Intersect332: ToIntersect1 Plane231, ToIntersect2 Plane220
  Trim196: Trimmed (Intersect332; Intersect329)
  Trim197: Trimmed (Trim196; Intersect331)
  Trim198: Trimmed (Trim197; Intersect330)
  Pocket71: profile Trim198, up to Plane228, deactivated
  Intersect333: ToIntersect1 Plane229, ToIntersect2 Plane222
  Intersect334: ToIntersect1 Plane230, ToIntersect2 Plane222
  Intersect335: ToIntersect1 Plane222, ToIntersect2 Plane228
  Intersect336: ToIntersect1 Plane231, ToIntersect2 Plane222
  Trim199: Trimmed (Intersect333; Intersect336)
  Trim200: Trimmed (Trim199; Intersect335)
  Trim201: Trimmed (Trim200; Intersect334)
  Pad68: profile LineCorner17, up to Plane223, opposite side up to Plane224, deactivated
  Pocket72: profile Trim201, up to Plane227, deactivated
  Intersect337: ToIntersect1 Plane228, ToIntersect2 Plane221
  Intersect338: ToIntersect1 Plane230, ToIntersect2 Plane221
  Intersect339: ToIntersect1 Plane229, ToIntersect2 Plane221
  Intersect340: ToIntersect1 Plane231, ToIntersect2 Plane221
  Trim202: Trimmed (Intersect337; Intersect340)
  Trim203: Trimmed (Trim202; Intersect339)
  Trim204: Trimmed (Trim203; Intersect338)
  Pad69: profile LineCorner17, up to Plane223, opposite side up to Plane224, deactivated
  Pocket73: profile Trim204, up to Plane226, deactivated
